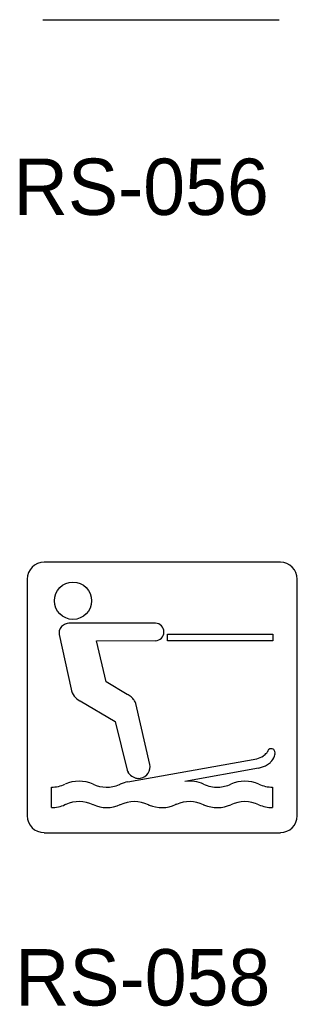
# Model space of a CAD drawing. Extents: x 42133 to 45533, y 41351 to 47951.
# Drawn here: x 43052.5 to 43089.5, y 41676.2 to 41807.4 of the extents above; entities that cross this region are included whole.
import ezdxf

# ---------------------------------------------------------------- set-up
doc = ezdxf.new("R2010")
doc.units = 0
doc.layers.add('P_TRAF_SIGN_SignDetails', color=7, linetype='Continuous')

msp = doc.modelspace()

# ---------------------------------------------------------------- linework, layer by layer
at = {"layer": 'P_TRAF_SIGN_SignDetails'}
for p, q in [((43055.58, 41807.42), (43087.05, 41807.42)), ((43087.23, 41735.24), (43055.76, 41735.24)), ((43053.51, 41732.99), (43053.51, 41701.5)), ((43089.48, 41701.5), (43089.48, 41732.99)), ((43055.76, 41699.25), (43087.23, 41699.25))]:
    msp.add_line(p, q, dxfattribs=at)
for points in [[(43070.58, 41727.12), (43059.28, 41727.12)], [(43070.58, 41727.12), (43059.28, 41727.12)], [(43070.58, 41727.12), (43059.28, 41727.12)], [(43057.77, 41725.61), (43059.37, 41718.36)], [(43057.77, 41725.61), (43059.37, 41718.36)], [(43057.77, 41725.61), (43059.37, 41718.36)], [(43066.81, 41717.65), (43064.02, 41719.32), (43062.75, 41724.8), (43070.58, 41724.81)], [(43066.81, 41717.65), (43064.02, 41719.32), (43062.75, 41724.8), (43070.58, 41724.81)], [(43066.81, 41717.65), (43064.02, 41719.32), (43062.75, 41724.8), (43070.58, 41724.81)], [(43060.54, 41716.8), (43060.57, 41716.79), (43065.24, 41714.06), (43066.83, 41707.57)], [(43060.54, 41716.8), (43060.57, 41716.79), (43065.24, 41714.06), (43066.83, 41707.57)], [(43060.54, 41716.8), (43060.57, 41716.79), (43065.24, 41714.06), (43066.83, 41707.57)], [(43069.89, 41708.06), (43069.86, 41708.32), (43067.97, 41716.43)], [(43069.89, 41708.06), (43069.86, 41708.32), (43067.97, 41716.43)], [(43069.89, 41708.06), (43069.86, 41708.32), (43067.97, 41716.43)], [(43066.92, 41706.03), (43084.08, 41709.08)], [(43066.92, 41706.03), (43084.08, 41709.08)], [(43066.92, 41706.03), (43084.08, 41709.08)], [(43084.31, 41707.84), (43074.49, 41706.07)], [(43084.31, 41707.84), (43074.49, 41706.07)], [(43084.31, 41707.84), (43074.49, 41706.07)], [(43068.32, 41706.49), (43068.3, 41706.48)], [(43068.32, 41706.49), (43068.3, 41706.48)], [(43068.32, 41706.49), (43068.3, 41706.48)], [(43056.73, 41702.59), (43056.73, 41705.31)], [(43056.73, 41702.59), (43056.73, 41705.31)], [(43056.73, 41702.59), (43056.73, 41705.31)], [(43086.18, 41705.31), (43086.18, 41702.59)], [(43086.18, 41705.31), (43086.18, 41702.59)], [(43086.18, 41705.31), (43086.18, 41702.59)]]:
    msp.add_lwpolyline(points, dxfattribs=at)
msp.add_lwpolyline([(43072.21, 41725.66), (43086.21, 41725.66), (43086.21, 41724.8), (43072.21, 41724.8)], close=True, dxfattribs=at)
msp.add_lwpolyline([(43072.21, 41725.66), (43086.21, 41725.66), (43086.21, 41724.8), (43072.21, 41724.8)], close=True, dxfattribs=at)
msp.add_lwpolyline([(43072.21, 41725.66), (43086.21, 41725.66), (43086.21, 41724.8), (43072.21, 41724.8)], close=True, dxfattribs=at)
msp.add_circle((43059.61, 41730.11), 2.48, dxfattribs=at)
msp.add_circle((43059.61, 41730.11), 2.48, dxfattribs=at)
msp.add_circle((43059.61, 41730.11), 2.48, dxfattribs=at)
for centre, radius, start, end in [((43055.76, 41732.98), 2.25, 90, 180), ((43087.23, 41732.98), 2.25, 360, 90), ((43058.99, 41725.82), 1.24, 121.6279, 181.9632), ((43058.99, 41725.82), 1.24, 121.6279, 181.9632), ((43058.99, 41725.82), 1.24, 121.6279, 181.9632), ((43059.17, 41725.55), 1.56, 101.9374, 122.0456), ((43059.17, 41725.55), 1.56, 101.9374, 122.0456), ((43059.17, 41725.55), 1.56, 101.9374, 122.0456), ((43059.28, 41725.06), 2.06, 89.7506, 102.0654), ((43059.28, 41725.06), 2.06, 89.7506, 102.0654), ((43059.28, 41725.06), 2.06, 89.7506, 102.0654), ((43070.57, 41725.96), 1.16, 270.0515, 89.9485), ((43070.57, 41725.96), 1.16, 270.0515, 89.9485), ((43070.57, 41725.96), 1.16, 270.0515, 89.9485), ((43058.93, 41725.82), 1.18, 182.4157, 190.5689), ((43058.93, 41725.82), 1.18, 182.4157, 190.5689), ((43058.93, 41725.82), 1.18, 182.4157, 190.5689), ((43061.49, 41718.74), 2.16, 190.2844, 243.9573), ((43061.49, 41718.74), 2.16, 190.2844, 243.9573), ((43061.49, 41718.74), 2.16, 190.2844, 243.9573), ((43066.11, 41715.92), 1.87, 58.3136, 68.017), ((43066.11, 41715.92), 1.87, 58.3136, 68.017), ((43066.11, 41715.92), 1.87, 58.3136, 68.017), ((43065.91, 41715.62), 2.23, 41.0728, 58.1307), ((43065.91, 41715.62), 2.23, 41.0728, 58.1307), ((43065.91, 41715.62), 2.23, 41.0728, 58.1307), ((43066.08, 41715.75), 2.02, 27.3814, 41.3884), ((43066.08, 41715.75), 2.02, 27.3814, 41.3884), ((43066.08, 41715.75), 2.02, 27.3814, 41.3884), ((43066.46, 41715.95), 1.59, 17.7906, 27.2883), ((43066.46, 41715.95), 1.59, 17.7906, 27.2883), ((43066.46, 41715.95), 1.59, 17.7906, 27.2883), ((43083.83, 41711.19), 2.05, 303.6915, 320.2732), ((43083.83, 41711.19), 2.05, 303.6915, 320.2732), ((43083.83, 41711.19), 2.05, 303.6915, 320.2732), ((43084.23, 41710.85), 1.53, 320.4935, 337.771), ((43084.23, 41710.85), 1.53, 320.4935, 337.771), ((43084.23, 41710.85), 1.53, 320.4935, 337.771), ((43085.82, 41710.2), 0.188, 130.5633, 157.8589), ((43085.82, 41710.2), 0.188, 130.5633, 157.8589), ((43085.82, 41710.2), 0.188, 130.5633, 157.8589), ((43085.87, 41710.15), 0.252, 117.3411, 130.7838), ((43085.87, 41710.15), 0.252, 117.3411, 130.7838), ((43085.87, 41710.15), 0.252, 117.3411, 130.7838), ((43085.92, 41710.05), 0.368, 105.4032, 117.335), ((43085.92, 41710.05), 0.368, 105.4032, 117.335), ((43085.92, 41710.05), 0.368, 105.4032, 117.335), ((43085.96, 41709.92), 0.5, 100.7736, 105.7777), ((43085.96, 41709.92), 0.5, 100.7736, 105.7777), ((43085.96, 41709.92), 0.5, 100.7736, 105.7777), ((43085.98, 41709.79), 0.637, 94.0613, 100.7537), ((43085.98, 41709.79), 0.637, 94.0613, 100.7537), ((43085.98, 41709.79), 0.637, 94.0613, 100.7537), ((43086, 41709.62), 0.799, 86.749, 94.1417), ((43086, 41709.62), 0.799, 86.749, 94.1417), ((43086, 41709.62), 0.799, 86.749, 94.1417), ((43086.02, 41709.93), 0.492, 35.7287, 87.3895), ((43086.02, 41709.93), 0.492, 35.7287, 87.3895), ((43086.02, 41709.93), 0.492, 35.7287, 87.3895), ((43085.97, 41709.89), 0.554, 359.6872, 35.9421), ((43085.97, 41709.89), 0.554, 359.6872, 35.9421), ((43085.97, 41709.89), 0.554, 359.6872, 35.9421), ((43084.9, 41709.96), 1.63, 341.325, 352.4962), ((43084.9, 41709.96), 1.63, 341.325, 352.4962), ((43084.9, 41709.96), 1.63, 341.325, 352.4962), ((43085.42, 41709.89), 1.1, 352.4025, 359.9162), ((43085.42, 41709.89), 1.1, 352.4025, 359.9162), ((43085.42, 41709.89), 1.1, 352.4025, 359.9162), ((43083.43, 41711.77), 2.76, 283.5158, 303.9258), ((43083.43, 41711.77), 2.76, 283.5158, 303.9258), ((43083.43, 41711.77), 2.76, 283.5158, 303.9258), ((43084.15, 41710.44), 2.54, 299.1565, 313.9083), ((43084.15, 41710.44), 2.54, 299.1565, 313.9083), ((43084.15, 41710.44), 2.54, 299.1565, 313.9083), ((43084.5, 41710.1), 2.05, 313.6498, 341.1575), ((43084.5, 41710.1), 2.05, 313.6498, 341.1575), ((43084.5, 41710.1), 2.05, 313.6498, 341.1575), ((43067.84, 41707.81), 1.04, 193.2924, 209.8171), ((43067.84, 41707.81), 1.04, 193.2924, 209.8171), ((43067.84, 41707.81), 1.04, 193.2924, 209.8171), ((43068.22, 41708.03), 1.48, 209.9302, 229.5299), ((43068.22, 41708.03), 1.48, 209.9302, 229.5299), ((43068.22, 41708.03), 1.48, 209.9302, 229.5299), ((43068.3, 41708.06), 1.59, 270.0063, 359.9722), ((43068.3, 41708.06), 1.59, 270.0063, 359.9722), ((43068.3, 41708.06), 1.59, 270.0063, 359.9722), ((43083.49, 41711.92), 4.16, 281.3812, 289.4052), ((43083.49, 41711.92), 4.16, 281.3812, 289.4052), ((43083.49, 41711.92), 4.16, 281.3812, 289.4052), ((43083.79, 41711.08), 3.27, 289.2883, 299.28), ((43083.79, 41711.08), 3.27, 289.2883, 299.28), ((43083.79, 41711.08), 3.27, 289.2883, 299.28), ((43060.42, 41701.72), 4.39, 64.8401, 115.1599), ((43060.42, 41701.72), 4.39, 64.8401, 115.1599), ((43060.42, 41701.72), 4.39, 64.8401, 115.1599), ((43067.81, 41701.61), 4.51, 101.3904, 114.909), ((43067.81, 41701.61), 4.51, 101.3904, 114.909), ((43067.81, 41701.61), 4.51, 101.3904, 114.909), ((43068.39, 41708.2), 1.72, 228.979, 256.7566), ((43068.39, 41708.2), 1.72, 228.979, 256.7566), ((43068.39, 41708.2), 1.72, 228.979, 256.7566), ((43068.32, 41707.95), 1.47, 257.0953, 269.8123), ((43068.32, 41707.95), 1.47, 257.0953, 269.8123), ((43068.32, 41707.95), 1.47, 257.0953, 269.8123), ((43075.14, 41701.72), 4.4, 64.8767, 98.473), ((43075.14, 41701.72), 4.4, 64.8767, 98.473), ((43075.14, 41701.72), 4.4, 64.8767, 98.473), ((43082.5, 41701.72), 4.39, 64.8357, 115.1643), ((43082.5, 41701.72), 4.39, 64.8357, 115.1643), ((43082.5, 41701.72), 4.39, 64.8357, 115.1643), ((43056.72, 41709.75), 4.44, 270.1544, 294.2709), ((43056.72, 41709.75), 4.44, 270.1544, 294.2709), ((43056.72, 41709.75), 4.44, 270.1544, 294.2709), ((43064.1, 41709.69), 4.38, 245.5804, 292.9527), ((43064.1, 41709.69), 4.38, 245.5804, 292.9527), ((43064.1, 41709.69), 4.38, 245.5804, 292.9527), ((43064.05, 41709.85), 4.55, 292.696, 294.126), ((43064.05, 41709.85), 4.55, 292.696, 294.126), ((43064.05, 41709.85), 4.55, 292.696, 294.126), ((43078.83, 41709.75), 4.44, 245.75, 271.4126), ((43078.83, 41709.75), 4.44, 245.75, 271.4126), ((43078.83, 41709.75), 4.44, 245.75, 271.4126), ((43078.81, 41709.76), 4.45, 271.733, 294.2367), ((43078.81, 41709.76), 4.45, 271.733, 294.2367), ((43078.81, 41709.76), 4.45, 271.733, 294.2367), ((43086.2, 41709.76), 4.45, 245.7583, 269.8242), ((43086.2, 41709.76), 4.45, 245.7583, 269.8242), ((43086.2, 41709.76), 4.45, 245.7583, 269.8242), ((43060.42, 41699.01), 4.38, 64.7917, 113.6905), ((43060.42, 41699.01), 4.38, 64.7917, 113.6905), ((43060.42, 41699.01), 4.38, 64.7917, 113.6905), ((43067.78, 41699.01), 4.38, 64.7819, 115.2181), ((43067.78, 41699.01), 4.38, 64.7819, 115.2181), ((43067.78, 41699.01), 4.38, 64.7819, 115.2181), ((43075.14, 41699.01), 4.38, 64.787, 113.6951), ((43075.14, 41699.01), 4.38, 64.787, 113.6951), ((43075.14, 41699.01), 4.38, 64.787, 113.6951), ((43082.5, 41699.01), 4.38, 64.7822, 115.2178), ((43082.5, 41699.01), 4.38, 64.7822, 115.2178), ((43082.5, 41699.01), 4.38, 64.7822, 115.2178), ((43056.72, 41707.05), 4.46, 270.1641, 294.1711), ((43056.72, 41707.05), 4.46, 270.1641, 294.1711), ((43056.72, 41707.05), 4.46, 270.1641, 294.1711), ((43060.47, 41698.83), 4.57, 113.4427, 114.9131), ((43060.47, 41698.83), 4.57, 113.4427, 114.9131), ((43060.47, 41698.83), 4.57, 113.4427, 114.9131), ((43064.1, 41706.99), 4.4, 245.6646, 294.3354), ((43064.1, 41706.99), 4.4, 245.6646, 294.3354), ((43064.1, 41706.99), 4.4, 245.6646, 294.3354), ((43071.51, 41707.16), 4.58, 245.958, 247.3806), ((43071.51, 41707.16), 4.58, 245.958, 247.3806), ((43071.51, 41707.16), 4.58, 245.958, 247.3806), ((43071.46, 41706.99), 4.4, 247.132, 294.3321), ((43071.46, 41706.99), 4.4, 247.132, 294.3321), ((43071.46, 41706.99), 4.4, 247.132, 294.3321), ((43075.19, 41698.86), 4.55, 113.4577, 114.9355), ((43075.19, 41698.86), 4.55, 113.4577, 114.9355), ((43075.19, 41698.86), 4.55, 113.4577, 114.9355), ((43078.87, 41707.16), 4.58, 245.952, 247.3742), ((43078.87, 41707.16), 4.58, 245.952, 247.3742), ((43078.87, 41707.16), 4.58, 245.952, 247.3742), ((43078.82, 41706.99), 4.4, 247.1425, 294.321), ((43078.82, 41706.99), 4.4, 247.1425, 294.321), ((43078.82, 41706.99), 4.4, 247.1425, 294.321), ((43086.19, 41707.03), 4.44, 245.7882, 269.8844), ((43086.19, 41707.03), 4.44, 245.7882, 269.8844), ((43086.19, 41707.03), 4.44, 245.7882, 269.8844), ((43055.76, 41701.51), 2.25, 180, 270), ((43087.23, 41701.51), 2.25, 270, 0)]:
    msp.add_arc(centre, radius, start, end, dxfattribs=at)

# ---------------------------------------------------------------- texts
for s, p in [('RS-056', (43051.69, 41781.44)), ('RS-058', (43051.89, 41676.26))]:
    msp.add_text(s, height=7.5, dxfattribs=at).set_placement(p)

doc.saveas('drawing.dxf')
